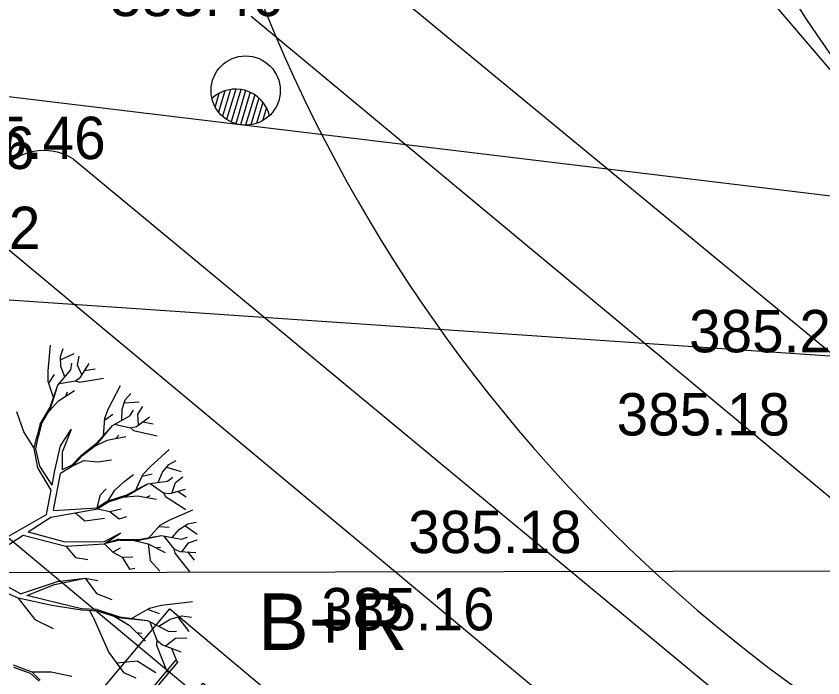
# Model space of a CAD drawing. Extents: x -438233 to -437334, y -1133133 to -1132623.
# Drawn here: x -438087.94 to -438073.66, y -1132974.1 to -1132962.38 of the extents above; entities that cross this region are included whole.
import ezdxf

# ---------------------------------------------------------------- set-up
doc = ezdxf.new("R2010")
doc.units = 0
for name, color, linetype in [('Default', 7, 'Continuous'), ('EL3', 7, 'Continuous'), ('MOBILIÁŘ', 7, 'Continuous'), ('OSY', 7, 'Continuous'), ('Vrstva 1', 7, 'Continuous'), ('Vrstva 10', 7, 'Continuous'), ('Vrstva 3', 7, 'Continuous'), ('Vrstva 40', 7, 'Continuous'), ('Vrstva 53', 7, 'Continuous')]:
    doc.layers.add(name, color=color, linetype=linetype)

# ---------------------------------------------------------------- blocks, each defined once
blk = doc.blocks.new('A$C73EC33FB')
at = {"layer": 'Default'}
for points in [[(-39000, 25012), (0, 25012), (0, 0), (-39000, 0)], [(-32310, 18759), (-31900, 18759), (-31900, 9105), (-32310, 9105)], [(-26014, 18759), (-25605, 18759), (-25605, 9105), (-26014, 9105)], [(-19705, 18759), (-19295, 18759), (-19295, 9105), (-19705, 9105)], [(-13409, 18759), (-13000, 18759), (-13000, 9105), (-13409, 9105)], [(-7100, 18759), (-6690, 18759), (-6690, 9105), (-7100, 9105)]]:
    blk.add_lwpolyline(points, close=True, dxfattribs=at)
blk = doc.blocks.new('ELJL31_2_1')
at = {"layer": 'EL3'}
for p, q in [((10.50516, 25), (24.4949, 25)), ((6.27724, 20), (28.72281, 20)), ((1.45902, 10), (33.54102, 10)), ((3.37727, 15), (31.62278, 15)), ((0, 0), (35, 0)), ((0.35902, 5), (34.64102, 5)), ((0.35902, -5), (34.64102, -5)), ((1.45902, -10), (33.54102, -10)), ((3.37727, -15), (31.62278, -15)), ((6.27724, -20), (28.72281, -20)), ((10.50516, -25), (24.4949, -25))]:
    blk.add_line(p, q, dxfattribs=at)
blk.add_circle((0, 0), 35, dxfattribs=at)
blk.add_arc((35, 0), 34.99996, 119.999947, 239.999954, dxfattribs=at)

msp = doc.modelspace()

# ---------------------------------------------------------------- linework, layer by layer
at = {"layer": 'OSY'}
msp.add_lwpolyline([(-438050.507, -1132933.894), (-438056.44, -1132932.473), (-438062.522, -1132932.954), (-438068.157, -1132935.291), (-438072.795, -1132939.255), (-438075.98, -1132944.458), (-438077.402, -1132950.391), (-438076.921, -1132956.473), (-438074.584, -1132962.109), (-438070.62, -1132966.746), (-438065.417, -1132969.932), (-438059.484, -1132971.354), (-438053.402, -1132970.872), (-438047.766, -1132968.535), (-438043.129, -1132964.571), (-438039.943, -1132959.368), (-438038.521, -1132953.435), (-438039.002, -1132947.353), (-438041.339, -1132941.718), (-438045.304, -1132937.08)], close=True, dxfattribs=at)
at = {"layer": 'Vrstva 1'}
for p, q in [((-438083.784, -1132962.385), (-438083.784, -1132962.385)), ((-438086.926, -1132964.916), (-438086.926, -1132964.916)), ((-438087.377, -1132968.665), (-438087.333, -1132968.209)), ((-438087.16, -1132968.41), (-438087.111, -1132968.271)), ((-438087.151, -1132968.587), (-438087.16, -1132968.41)), ((-438087.156, -1132968.471), (-438086.916, -1132968.356)), ((-438086.857, -1132968.566), (-438086.83, -1132968.404)), ((-438087.082, -1132968.772), (-438087.151, -1132968.587)), ((-438086.978, -1132968.645), (-438086.956, -1132968.53)), ((-438086.78, -1132968.735), (-438086.857, -1132968.566)), ((-438086.802, -1132968.775), (-438086.648, -1132968.533)), ((-438087.376, -1132968.851), (-438087.377, -1132968.665)), ((-438087.365, -1132968.883), (-438087.267, -1132968.729)), ((-438087.204, -1132968.918), (-438086.978, -1132968.645)), ((-438086.727, -1132968.657), (-438086.544, -1132968.627)), ((-438087.278, -1132969.151), (-438087.376, -1132968.851)), ((-438087.177, -1132968.886), (-438086.891, -1132968.841)), ((-438086.891, -1132968.841), (-438086.802, -1132968.775)), ((-438086.891, -1132968.841), (-438086.821, -1132968.866)), ((-438086.821, -1132968.866), (-438086.396, -1132968.795)), ((-438087.343, -1132969.308), (-438087.204, -1132968.918)), ((-438087.335, -1132969.333), (-438087.204, -1132968.918)), ((-438087.193, -1132969.196), (-438086.908, -1132969.01)), ((-438086.307, -1132969.331), (-438086.098, -1132968.924)), ((-438087.063, -1132969.112), (-438087.035, -1132969.037)), ((-438086.011, -1132969.175), (-438085.914, -1132969.062)), ((-438087.364, -1132969.382), (-438087.193, -1132969.196)), ((-438086.069, -1132969.341), (-438086.011, -1132969.175)), ((-438086.031, -1132969.231), (-438085.765, -1132969.214)), ((-438085.789, -1132969.432), (-438085.702, -1132969.292)), ((-438087.806, -1132969.745), (-438087.933, -1132969.389)), ((-438087.518, -1132969.609), (-438087.343, -1132969.308)), ((-438087.492, -1132969.599), (-438087.335, -1132969.333)), ((-438086.377, -1132969.537), (-438086.229, -1132969.432)), ((-438086.376, -1132969.504), (-438086.307, -1132969.331)), ((-438086.073, -1132969.539), (-438086.069, -1132969.341)), ((-438085.929, -1132969.46), (-438085.868, -1132969.361)), ((-438085.779, -1132969.618), (-438085.789, -1132969.432)), ((-438086.397, -1132969.819), (-438086.376, -1132969.504)), ((-438086.24, -1132969.63), (-438085.929, -1132969.46)), ((-438085.814, -1132969.646), (-438085.581, -1132969.478)), ((-438085.701, -1132969.565), (-438085.52, -1132969.604)), ((-438087.518, -1132969.609), (-438087.576, -1132969.833)), ((-438087.492, -1132969.599), (-438087.554, -1132969.838)), ((-438087.158, -1132969.991), (-438086.969, -1132969.701)), ((-438086.969, -1132969.701), (-438087.131, -1132970.101)), ((-438086.517, -1132969.966), (-438086.24, -1132969.63)), ((-438086.514, -1132969.94), (-438086.24, -1132969.63)), ((-438086.203, -1132969.609), (-438085.921, -1132969.675)), ((-438085.921, -1132969.675), (-438085.814, -1132969.646)), ((-438085.921, -1132969.675), (-438085.865, -1132969.722)), ((-438085.865, -1132969.722), (-438085.445, -1132969.816)), ((-438087.622, -1132970.035), (-438087.806, -1132969.745)), ((-438087.622, -1132970.035), (-438087.576, -1132969.833)), ((-438087.593, -1132970.046), (-438087.554, -1132969.838)), ((-438086.334, -1132969.893), (-438086, -1132969.824)), ((-438086.181, -1132969.861), (-438086.127, -1132969.803)), ((-438074.815, -1132969.808), (-438074.815, -1132969.808)), ((-438087.256, -1132970.428), (-438087.158, -1132969.991)), ((-438086.789, -1132970.155), (-438086.514, -1132969.94)), ((-438086.76, -1132970.157), (-438086.517, -1132969.966)), ((-438086.563, -1132970.001), (-438086.334, -1132969.893)), ((-438087.561, -1132970.381), (-438087.622, -1132970.035)), ((-438087.523, -1132970.352), (-438087.593, -1132970.046)), ((-438087.131, -1132970.101), (-438087.126, -1132970.418)), ((-438086.789, -1132970.155), (-438086.955, -1132970.331)), ((-438086.76, -1132970.157), (-438086.944, -1132970.352)), ((-438085.573, -1132970.363), (-438085.232, -1132970.056)), ((-438086.737, -1132970.251), (-438086.944, -1132970.352)), ((-438086.737, -1132970.251), (-438086.495, -1132970.277)), ((-438086.495, -1132970.277), (-438086.255, -1132970.239)), ((-438085.241, -1132970.322), (-438085.111, -1132970.252)), ((-438087.324, -1132970.775), (-438087.561, -1132970.381)), ((-438087.306, -1132970.686), (-438087.523, -1132970.352)), ((-438087.306, -1132970.686), (-438087.256, -1132970.428)), ((-438086.944, -1132970.352), (-438087.156, -1132970.483)), ((-438086.955, -1132970.331), (-438087.126, -1132970.418)), ((-438085.698, -1132970.501), (-438085.573, -1132970.363)), ((-438085.353, -1132970.457), (-438085.241, -1132970.322)), ((-438085.279, -1132970.368), (-438085.024, -1132970.445)), ((-438087.28, -1132971.132), (-438087.156, -1132970.483)), ((-438086.037, -1132970.626), (-438085.863, -1132970.499)), ((-438085.828, -1132970.788), (-438085.698, -1132970.501)), ((-438085.711, -1132970.531), (-438085.534, -1132970.485)), ((-438085.427, -1132970.64), (-438085.353, -1132970.457)), ((-438085.265, -1132970.617), (-438085.171, -1132970.546)), ((-438085.123, -1132970.641), (-438084.993, -1132970.541)), ((-438086.198, -1132970.773), (-438086.037, -1132970.626)), ((-438085.993, -1132970.883), (-438085.616, -1132970.666)), ((-438085.981, -1132970.86), (-438085.616, -1132970.666)), ((-438085.616, -1132970.666), (-438085.265, -1132970.617)), ((-438085.573, -1132970.66), (-438085.333, -1132970.821)), ((-438085.18, -1132970.818), (-438085.123, -1132970.641)), ((-438087.408, -1132971.206), (-438087.324, -1132970.775)), ((-438086.508, -1132971.089), (-438086.451, -1132970.859)), ((-438086.451, -1132970.859), (-438086.348, -1132970.75)), ((-438086.314, -1132970.964), (-438086.198, -1132970.773)), ((-438086.314, -1132970.964), (-438085.981, -1132970.86)), ((-438085.643, -1132970.903), (-438085.571, -1132970.869)), ((-438085.333, -1132970.821), (-438085.297, -1132970.886)), ((-438085.333, -1132970.821), (-438085.223, -1132970.832)), ((-438085.223, -1132970.832), (-438084.946, -1132970.757)), ((-438085.088, -1132970.796), (-438084.932, -1132970.896)), ((-438086.314, -1132970.964), (-438086.508, -1132971.089)), ((-438086.288, -1132970.975), (-438086.496, -1132971.109)), ((-438086.288, -1132970.975), (-438085.993, -1132970.883)), ((-438086.049, -1132970.9), (-438085.796, -1132970.878)), ((-438085.796, -1132970.878), (-438085.46, -1132970.933)), ((-438085.297, -1132970.886), (-438084.937, -1132971.121)), ((-438087.331, -1132971.256), (-438086.496, -1132971.109)), ((-438087.282, -1132971.133), (-438086.508, -1132971.089)), ((-438086.496, -1132971.109), (-438086.284, -1132971.152)), ((-438086.284, -1132971.152), (-438086.086, -1132971.108)), ((-438086.284, -1132971.152), (-438086.122, -1132971.285)), ((-438085.233, -1132971.305), (-438084.813, -1132971.122)), ((-438088.505, -1132971.834), (-438087.408, -1132971.206)), ((-438087.731, -1132971.515), (-438087.331, -1132971.256)), ((-438086.891, -1132971.178), (-438086.728, -1132971.318)), ((-438086.728, -1132971.318), (-438086.377, -1132971.272)), ((-438086.122, -1132971.285), (-438085.985, -1132971.24)), ((-438085.395, -1132971.398), (-438085.233, -1132971.305)), ((-438085.609, -1132971.629), (-438085.395, -1132971.398)), ((-438085.417, -1132971.421), (-438085.235, -1132971.433)), ((-438085.054, -1132971.465), (-438084.905, -1132971.37)), ((-438084.955, -1132971.403), (-438084.738, -1132971.557)), ((-438084.905, -1132971.37), (-438084.758, -1132971.345)), ((-438088.453, -1132971.984), (-438087.819, -1132971.573)), ((-438087.819, -1132971.573), (-438087.062, -1132971.769)), ((-438087.731, -1132971.515), (-438087.081, -1132971.692)), ((-438086.377, -1132971.685), (-438086.092, -1132971.53)), ((-438086.377, -1132971.728), (-438086.092, -1132971.53)), ((-438085.795, -1132971.667), (-438085.369, -1132971.58)), ((-438085.777, -1132971.649), (-438085.369, -1132971.58)), ((-438085.369, -1132971.58), (-438085.019, -1132971.644)), ((-438085.327, -1132971.588), (-438085.15, -1132971.816)), ((-438085.182, -1132971.615), (-438085.054, -1132971.465)), ((-438087.081, -1132971.692), (-438086.377, -1132971.685)), ((-438087.062, -1132971.769), (-438086.377, -1132971.728)), ((-438086.126, -1132971.642), (-438086.377, -1132971.728)), ((-438086.104, -1132971.661), (-438086.377, -1132971.728)), ((-438086.377, -1132971.728), (-438086.231, -1132971.873)), ((-438086.126, -1132971.642), (-438085.777, -1132971.649)), ((-438086.104, -1132971.661), (-438085.795, -1132971.667)), ((-438085.853, -1132971.665), (-438085.607, -1132971.725)), ((-438085.607, -1132971.725), (-438085.569, -1132972.022)), ((-438085.607, -1132971.725), (-438085.306, -1132971.882)), ((-438085.019, -1132971.644), (-438084.91, -1132971.607)), ((-438085.004, -1132971.861), (-438084.894, -1132971.711)), ((-438084.894, -1132971.711), (-438084.739, -1132971.657)), ((-438087.062, -1132971.769), (-438086.892, -1132971.97)), ((-438086.231, -1132971.873), (-438086.095, -1132971.797)), ((-438086.231, -1132971.873), (-438086.069, -1132971.961)), ((-438085.469, -1132971.798), (-438085.39, -1132971.786)), ((-438085.15, -1132971.816), (-438085.136, -1132971.889)), ((-438085.15, -1132971.816), (-438085.048, -1132971.861)), ((-438085.048, -1132971.861), (-438084.763, -1132971.878)), ((-438084.909, -1132971.869), (-438084.794, -1132972.014)), ((-438086.892, -1132971.97), (-438086.676, -1132972.001)), ((-438086.069, -1132971.961), (-438085.877, -1132971.955)), ((-438086.069, -1132971.961), (-438085.936, -1132972.175)), ((-438085.136, -1132971.889), (-438084.868, -1132972.226)), ((-438078.503, -1132971.89), (-438078.503, -1132971.89)), ((-438085.936, -1132972.175), (-438085.843, -1132972.157)), ((-438085.569, -1132972.022), (-438085.402, -1132972.208)), ((-438087.868, -1132972.611), (-438088.246, -1132972.407)), ((-438087.868, -1132972.611), (-438087.214, -1132972.394)), ((-438087.752, -1132972.64), (-438087.262, -1132972.443)), ((-438087.262, -1132972.443), (-438086.723, -1132972.332)), ((-438087.214, -1132972.394), (-438086.723, -1132972.332)), ((-438086.723, -1132972.332), (-438086.522, -1132972.604)), ((-438086.723, -1132972.332), (-438086.497, -1132972.373)), ((-438087.908, -1132972.685), (-438088.279, -1132972.524)), ((-438087.908, -1132972.685), (-438087.615, -1132973.063)), ((-438087.313, -1132972.816), (-438087.908, -1132972.685)), ((-438087.393, -1132972.727), (-438087.752, -1132972.64)), ((-438086.787, -1132972.874), (-438087.393, -1132972.727)), ((-438086.522, -1132972.604), (-438086.252, -1132972.712)), ((-438086.789, -1132972.902), (-438087.313, -1132972.816)), ((-438086.51, -1132972.886), (-438086.787, -1132972.874)), ((-438085.912, -1132973.052), (-438085.585, -1132972.862)), ((-438085.585, -1132972.862), (-438085.368, -1132972.814)), ((-438085.368, -1132972.814), (-438084.821, -1132972.749)), ((-438086.492, -1132972.915), (-438086.789, -1132972.902)), ((-438086.579, -1132973.023), (-438086.636, -1132972.909)), ((-438086.51, -1132972.886), (-438086.112, -1132973.016)), ((-438086.492, -1132972.915), (-438086.139, -1132973.031)), ((-438086.206, -1132973.009), (-438085.944, -1132973.163)), ((-438086.112, -1132973.016), (-438085.62, -1132973.081)), ((-438085.619, -1132972.882), (-438085.414, -1132972.959)), ((-438085.218, -1132973.059), (-438085.013, -1132973.003)), ((-438085.013, -1132973.003), (-438084.837, -1132973.025)), ((-438087.615, -1132973.063), (-438087.285, -1132973.227)), ((-438086.579, -1132973.023), (-438086.301, -1132973.648)), ((-438086.139, -1132973.031), (-438085.62, -1132973.081)), ((-438085.62, -1132973.081), (-438085.242, -1132973.277)), ((-438085.575, -1132973.104), (-438085.451, -1132973.429)), ((-438085.418, -1132973.185), (-438085.218, -1132973.059)), ((-438085.083, -1132973.023), (-438084.888, -1132973.276)), ((-438085.944, -1132973.163), (-438085.652, -1132973.45)), ((-438085.81, -1132973.294), (-438085.717, -1132973.31)), ((-438085.242, -1132973.277), (-438085.102, -1132973.272)), ((-438080.042, -1132973.257), (-438080.042, -1132973.257)), ((-438085.451, -1132973.429), (-438085.461, -1132973.517)), ((-438085.451, -1132973.429), (-438085.351, -1132973.516)), ((-438085.299, -1132973.532), (-438085.12, -1132973.398)), ((-438085.12, -1132973.398), (-438084.923, -1132973.39)), ((-438085.461, -1132973.517), (-438085.271, -1132973.998)), ((-438085.351, -1132973.516), (-438085.027, -1132973.635)), ((-438085.194, -1132973.574), (-438085.111, -1132973.78)), ((-438086.301, -1132973.648), (-438086.044, -1132974.002)), ((-438087.994, -1132973.865), (-438087.668, -1132973.994)), ((-438086.169, -1132973.83), (-438085.803, -1132973.797)), ((-438085.803, -1132973.797), (-438085.469, -1132974.004)), ((-438087.989, -1132973.911), (-438087.693, -1132974.015)), ((-438087.693, -1132974.015), (-438087.537, -1132974.156)), ((-438087.668, -1132973.994), (-438087.326, -1132973.99)), ((-438087.668, -1132973.994), (-438087.52, -1132974.14)), ((-438087.326, -1132973.99), (-438086.955, -1132974.069)), ((-438086.044, -1132974.002), (-438085.827, -1132974.098))]:
    msp.add_line(p, q, dxfattribs=at)
for centre, radius, start, end in [((-438057.961, -1132951.909), 19.15, 161.159, 229.4804), ((-438057.962, -1132951.913), 27.6, 199.5386, 254.3601)]:
    msp.add_arc(centre, radius, start, end, dxfattribs=at)
at = {"layer": 'Vrstva 10'}
for points in [[(-438082.411, -1132961.014), (-438066.062, -1132974.491)], [(-438083.784, -1132962.385), (-438067.332, -1132976.054)], [(-438086.926, -1132964.916), (-438070.59, -1132978.455)], [(-438088.082, -1132966.508), (-438071.892, -1132980)], [(-438091.201, -1132969.023), (-438075.155, -1132982.388)]]:
    msp.add_lwpolyline(points, dxfattribs=at)
msp.add_arc((-438087.45, -1132965.751), 0.986, 57.9107, 230.1202, dxfattribs=at)
at = {"layer": 'Vrstva 40'}
msp.add_line((-438088.826, -1132972.232), (-438019.505, -1132972.094), dxfattribs=at)
msp.add_lwpolyline([(-438099.752, -1132962.397), (-438019.505, -1132972.094), (-438094.126, -1132966.999)], dxfattribs=at)

# ---------------------------------------------------------------- block references
at = {"layer": 'MOBILIÁŘ', "xscale": 0.0001, "yscale": 9.999999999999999e-05, "rotation": -39.966187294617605}
msp.add_blockref('A$C73EC33FB', (-438083.843, -1132977.3), dxfattribs=at)
at = {"layer": 'Vrstva 53', "xscale": 0.0175, "yscale": 0.0175, "rotation": -106.66592339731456}
msp.add_blockref('ELJL31_2_1', (-438083.881, -1132963.702), dxfattribs=at)

# ---------------------------------------------------------------- texts
at = {"layer": 'Vrstva 1'}
msp.add_text('B+R', height=1, dxfattribs=at).set_placement((-438083.658, -1132973.604))
at = {"layer": 'Vrstva 3'}
for s, p in [('385.46 ', (-438086.284, -1132962.385)), ('385.46 ', (-438089.426, -1132964.916)), ('385.46 ', (-438090.682, -1132965.091)), ('385.42 ', (-438090.582, -1132966.508)), ('385.22 ', (-438076.032, -1132968.336)), ('385.18 ', (-438077.315, -1132969.808)), ('385.18 ', (-438081.003, -1132971.89)), ('385.16 ', (-438082.542, -1132973.257))]:
    msp.add_text(s, height=0.75, dxfattribs=at).set_placement(p)

doc.saveas('drawing.dxf')
